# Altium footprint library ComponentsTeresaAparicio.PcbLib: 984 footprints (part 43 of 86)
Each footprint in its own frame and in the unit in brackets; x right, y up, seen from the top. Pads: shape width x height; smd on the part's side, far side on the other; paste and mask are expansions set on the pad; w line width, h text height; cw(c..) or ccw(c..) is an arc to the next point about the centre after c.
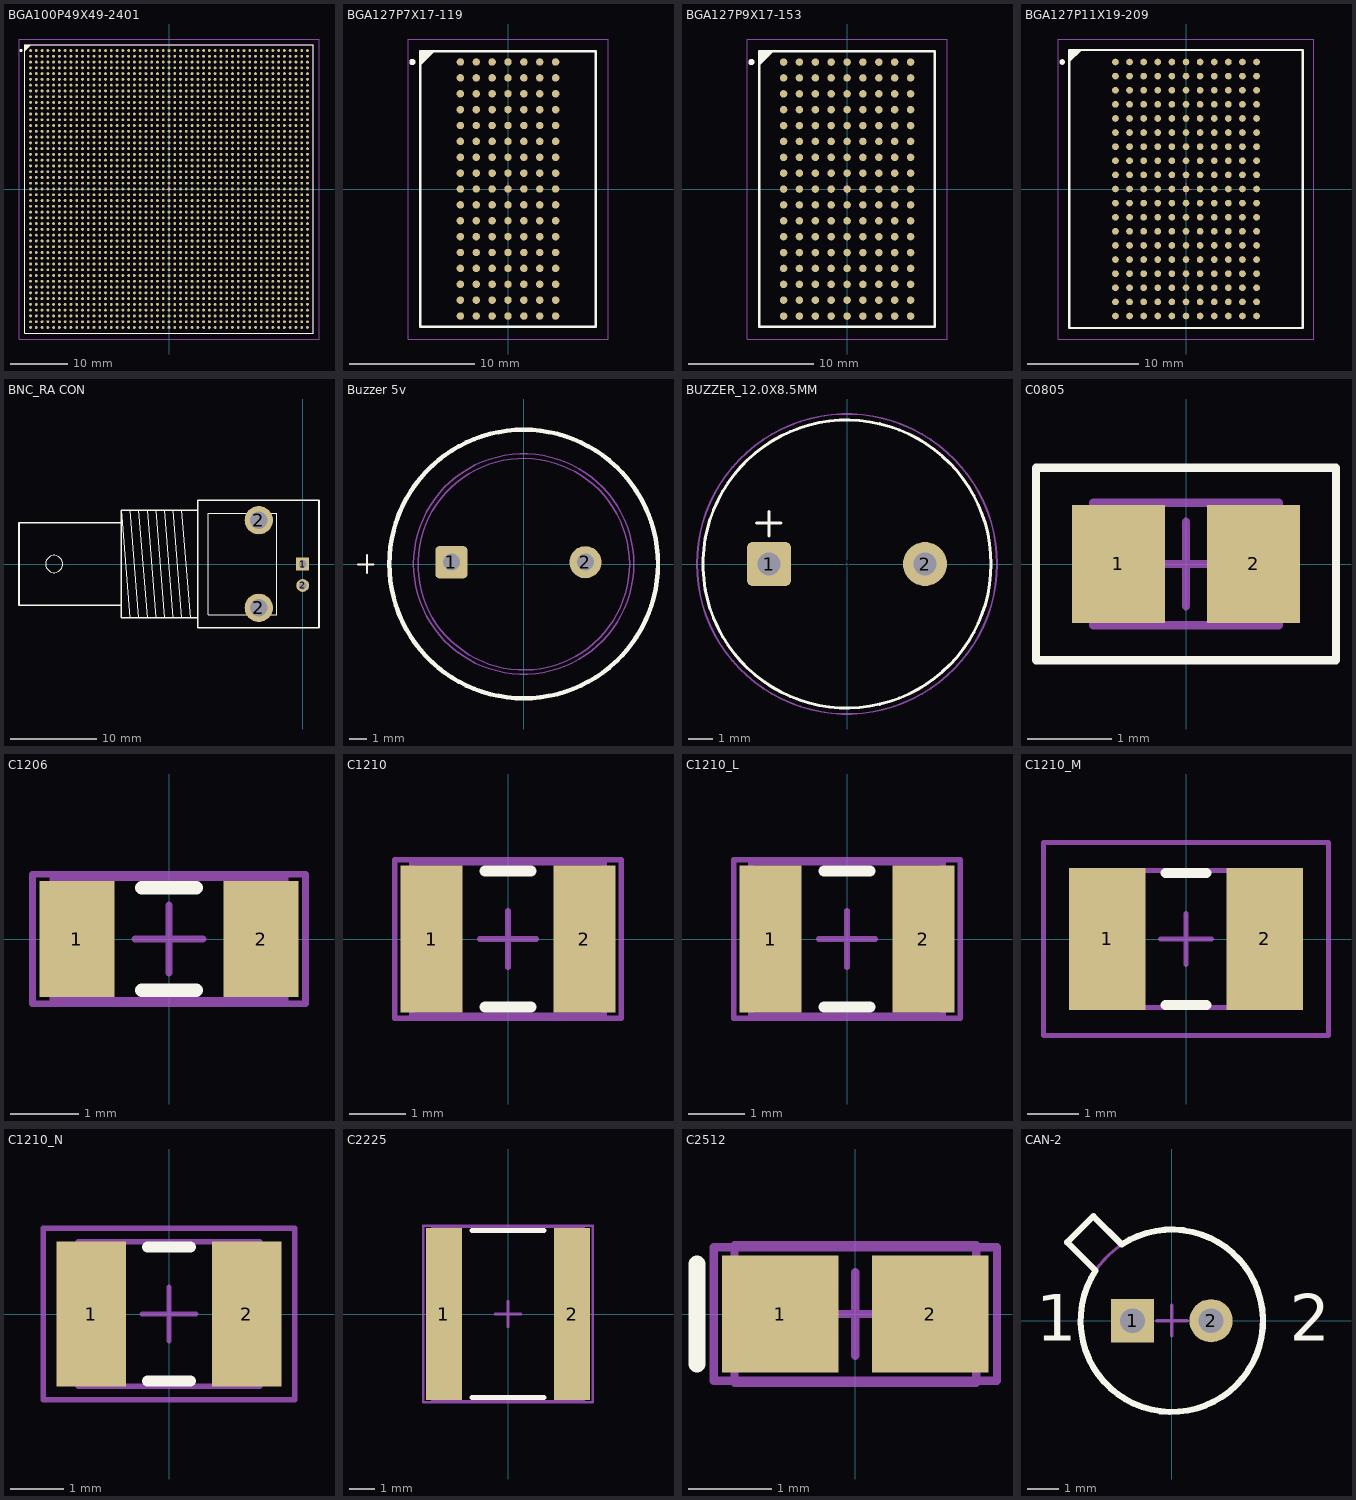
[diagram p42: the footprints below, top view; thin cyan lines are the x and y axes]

## BGA100P49X49-2401 [mm] "BGA, 2401-Leads, Body 50x50mm, Pitch 1mm"
height 3.5
pads (2401):
  round 0.5 smd: A1(-24,24) A2(-23,24) A3(-22,24) A4(-21,24) A5(-20,24) A6(-19,24) A7(-18,24) A8(-17,24) A9(-16,24) A10(-15,24) A11(-14,24) A12(-13,24) A13(-12,24) A14(-11,24) A15(-10,24) A16(-9,24) A17(-8,24) A18(-7,24) A19(-6,24) A20(-5,24) A21(-4,24) A22(-3,24) A23(-2,24) A24(-1,24) A25(0,24) A26(1,24) A27(2,24) A28(3,24) A29(4,24) A30(5,24) A31(6,24) A32(7,24) A33(8,24) A34(9,24) A35(10,24) A36(11,24) A37(12,24) A38(13,24) A39(14,24) A40(15,24) A41(16,24) A42(17,24) A43(18,24) A44(19,24) A45(20,24) A46(21,24) A47(22,24) A48(23,24) A49(24,24) AA1(-24,4) AA2(-23,4) AA3(-22,4) AA4(-21,4) AA5(-20,4) AA6(-19,4) AA7(-18,4) AA8(-17,4) AA9(-16,4) AA10(-15,4) AA11(-14,4) AA12(-13,4) AA13(-12,4) AA14(-11,4) AA15(-10,4) AA16(-9,4) AA17(-8,4) AA18(-7,4) AA19(-6,4) AA20(-5,4) AA21(-4,4) AA22(-3,4) AA23(-2,4) AA24(-1,4) AA25(0,4) AA26(1,4) AA27(2,4) AA28(3,4) AA29(4,4) AA30(5,4) AA31(6,4) AA32(7,4) AA33(8,4) AA34(9,4) AA35(10,4) AA36(11,4) AA37(12,4) AA38(13,4) AA39(14,4) AA40(15,4) AA41(16,4) AA42(17,4) AA43(18,4) AA44(19,4) AA45(20,4) AA46(21,4) AA47(22,4) AA48(23,4) AA49(24,4) AB1(-24,3) AB2(-23,3) AB3(-22,3) AB4(-21,3) AB5(-20,3) AB6(-19,3) AB7(-18,3) AB8(-17,3) AB9(-16,3) AB10(-15,3) AB11(-14,3) AB12(-13,3) AB13(-12,3) AB14(-11,3) AB15(-10,3) AB16(-9,3) AB17(-8,3) AB18(-7,3) AB19(-6,3) AB20(-5,3) AB21(-4,3) AB22(-3,3) AB23(-2,3) AB24(-1,3) AB25(0,3) AB26(1,3) AB27(2,3) AB28(3,3) AB29(4,3) AB30(5,3) AB31(6,3) AB32(7,3) AB33(8,3) AB34(9,3) AB35(10,3) AB36(11,3) AB37(12,3) AB38(13,3) AB39(14,3) AB40(15,3) AB41(16,3) AB42(17,3) AB43(18,3) AB44(19,3) AB45(20,3) AB46(21,3) AB47(22,3) AB48(23,3) AB49(24,3) AC1(-24,2) AC2(-23,2) AC3(-22,2) AC4(-21,2) AC5(-20,2) AC6(-19,2) AC7(-18,2) AC8(-17,2) AC9(-16,2) AC10(-15,2) AC11(-14,2) AC12(-13,2) AC13(-12,2) AC14(-11,2) AC15(-10,2) AC16(-9,2) AC17(-8,2) AC18(-7,2) AC19(-6,2) AC20(-5,2) AC21(-4,2) AC22(-3,2) AC23(-2,2) AC24(-1,2) AC25(0,2) AC26(1,2) AC27(2,2) AC28(3,2) AC29(4,2) AC30(5,2) AC31(6,2) AC32(7,2) AC33(8,2) AC34(9,2) AC35(10,2) AC36(11,2) AC37(12,2) AC38(13,2) AC39(14,2) AC40(15,2) AC41(16,2) AC42(17,2) AC43(18,2) AC44(19,2) AC45(20,2) AC46(21,2) AC47(22,2) AC48(23,2) AC49(24,2) AD1(-24,1) AD2(-23,1) AD3(-22,1) AD4(-21,1) AD5(-20,1) AD6(-19,1) AD7(-18,1) AD8(-17,1) AD9(-16,1) AD10(-15,1) AD11(-14,1) AD12(-13,1) AD13(-12,1) AD14(-11,1) AD15(-10,1) AD16(-9,1) AD17(-8,1) AD18(-7,1) AD19(-6,1) AD20(-5,1) AD21(-4,1) AD22(-3,1) AD23(-2,1) AD24(-1,1) AD25(0,1) AD26(1,1) AD27(2,1) AD28(3,1) AD29(4,1) AD30(5,1) AD31(6,1) AD32(7,1) AD33(8,1) AD34(9,1) AD35(10,1) AD36(11,1) AD37(12,1) AD38(13,1) AD39(14,1) AD40(15,1) AD41(16,1) AD42(17,1) AD43(18,1) AD44(19,1) AD45(20,1) AD46(21,1) AD47(22,1) AD48(23,1) AD49(24,1) AE1(-24,0) AE2(-23,0) AE3(-22,0) AE4(-21,0) AE5(-20,0) AE6(-19,0) AE7(-18,0) AE8(-17,0) AE9(-16,0) AE10(-15,0) AE11(-14,0) AE12(-13,0) AE13(-12,0) AE14(-11,0) AE15(-10,0) AE16(-9,0) AE17(-8,0) AE18(-7,0) AE19(-6,0) AE20(-5,0) AE21(-4,0) AE22(-3,0) AE23(-2,0) AE24(-1,0) AE25(0,0) AE26(1,0) AE27(2,0) AE28(3,0) AE29(4,0) AE30(5,0) AE31(6,0) AE32(7,0) AE33(8,0) AE34(9,0) AE35(10,0) AE36(11,0) AE37(12,0) AE38(13,0) AE39(14,0) AE40(15,0) AE41(16,0) AE42(17,0) AE43(18,0) AE44(19,0) AE45(20,0) AE46(21,0) AE47(22,0) AE48(23,0) AE49(24,0) AF1(-24,-1) AF2(-23,-1) AF3(-22,-1) AF4(-21,-1) AF5(-20,-1) AF6(-19,-1) AF7(-18,-1) AF8(-17,-1) AF9(-16,-1) AF10(-15,-1) AF11(-14,-1) AF12(-13,-1) AF13(-12,-1) AF14(-11,-1) AF15(-10,-1) AF16(-9,-1) AF17(-8,-1) AF18(-7,-1) AF19(-6,-1) AF20(-5,-1) AF21(-4,-1) AF22(-3,-1) AF23(-2,-1) AF24(-1,-1) AF25(0,-1) AF26(1,-1) AF27(2,-1) AF28(3,-1) AF29(4,-1) AF30(5,-1) AF31(6,-1) AF32(7,-1) AF33(8,-1) AF34(9,-1) AF35(10,-1) AF36(11,-1) AF37(12,-1) AF38(13,-1) AF39(14,-1) AF40(15,-1) AF41(16,-1) AF42(17,-1) AF43(18,-1) AF44(19,-1) AF45(20,-1) AF46(21,-1) AF47(22,-1) AF48(23,-1) AF49(24,-1) AG1(-24,-2) AG2(-23,-2) AG3(-22,-2) AG4(-21,-2) AG5(-20,-2) AG6(-19,-2) AG7(-18,-2) AG8(-17,-2) AG9(-16,-2) AG10(-15,-2) AG11(-14,-2) AG12(-13,-2) AG13(-12,-2) AG14(-11,-2) AG15(-10,-2) AG16(-9,-2) AG17(-8,-2) AG18(-7,-2) AG19(-6,-2) AG20(-5,-2) AG21(-4,-2) AG22(-3,-2) AG23(-2,-2) AG24(-1,-2) AG25(0,-2) AG26(1,-2) AG27(2,-2) AG28(3,-2) AG29(4,-2) AG30(5,-2) AG31(6,-2) AG32(7,-2) AG33(8,-2) AG34(9,-2) AG35(10,-2) AG36(11,-2) AG37(12,-2) AG38(13,-2) AG39(14,-2) AG40(15,-2) AG41(16,-2) AG42(17,-2) AG43(18,-2) AG44(19,-2) AG45(20,-2) AG46(21,-2) AG47(22,-2) AG48(23,-2) AG49(24,-2) AH1(-24,-3) AH2(-23,-3) AH3(-22,-3) AH4(-21,-3) AH5(-20,-3) AH6(-19,-3) AH7(-18,-3) AH8(-17,-3) AH9(-16,-3) AH10(-15,-3) AH11(-14,-3) AH12(-13,-3) AH13(-12,-3) AH14(-11,-3) AH15(-10,-3) AH16(-9,-3) AH17(-8,-3) AH18(-7,-3) AH19(-6,-3) AH20(-5,-3) AH21(-4,-3) AH22(-3,-3) AH23(-2,-3) AH24(-1,-3) AH25(0,-3) AH26(1,-3) AH27(2,-3) AH28(3,-3) AH29(4,-3) AH30(5,-3) AH31(6,-3) AH32(7,-3) AH33(8,-3) AH34(9,-3) AH35(10,-3) AH36(11,-3) AH37(12,-3) AH38(13,-3) AH39(14,-3) AH40(15,-3) AH41(16,-3) AH42(17,-3) AH43(18,-3) AH44(19,-3) AH45(20,-3) AH46(21,-3) AH47(22,-3) AH48(23,-3) AH49(24,-3) AJ1(-24,-4) AJ2(-23,-4) AJ3(-22,-4) AJ4(-21,-4) AJ5(-20,-4) AJ6(-19,-4) AJ7(-18,-4) AJ8(-17,-4) AJ9(-16,-4) AJ10(-15,-4) AJ11(-14,-4) AJ12(-13,-4) AJ13(-12,-4) AJ14(-11,-4) AJ15(-10,-4) AJ16(-9,-4) AJ17(-8,-4) AJ18(-7,-4) AJ19(-6,-4) AJ20(-5,-4) AJ21(-4,-4) AJ22(-3,-4) AJ23(-2,-4) AJ24(-1,-4) AJ25(0,-4) AJ26(1,-4) AJ27(2,-4) AJ28(3,-4) AJ29(4,-4) AJ30(5,-4) AJ31(6,-4) AJ32(7,-4) AJ33(8,-4) AJ34(9,-4) AJ35(10,-4) AJ36(11,-4) AJ37(12,-4) AJ38(13,-4) AJ39(14,-4) AJ40(15,-4) AJ41(16,-4) AJ42(17,-4) AJ43(18,-4) AJ44(19,-4) AJ45(20,-4) AJ46(21,-4) AJ47(22,-4) AJ48(23,-4) AJ49(24,-4) AK1(-24,-5) AK2(-23,-5) AK3(-22,-5) AK4(-21,-5) AK5(-20,-5) AK6(-19,-5) AK7(-18,-5) AK8(-17,-5) AK9(-16,-5) AK10(-15,-5) AK11(-14,-5) AK12(-13,-5) AK13(-12,-5) AK14(-11,-5) AK15(-10,-5) AK16(-9,-5) AK17(-8,-5) AK18(-7,-5) AK19(-6,-5) AK20(-5,-5) AK21(-4,-5) AK22(-3,-5) AK23(-2,-5) AK24(-1,-5) AK25(0,-5) AK26(1,-5) AK27(2,-5) AK28(3,-5) AK29(4,-5) AK30(5,-5) AK31(6,-5) AK32(7,-5) AK33(8,-5) AK34(9,-5) AK35(10,-5) AK36(11,-5) AK37(12,-5) AK38(13,-5) AK39(14,-5) AK40(15,-5) AK41(16,-5) AK42(17,-5) AK43(18,-5) AK44(19,-5) AK45(20,-5) AK46(21,-5) AK47(22,-5) AK48(23,-5) AK49(24,-5) AL1(-24,-6) AL2(-23,-6) AL3(-22,-6) AL4(-21,-6) AL5(-20,-6) AL6(-19,-6) AL7(-18,-6) AL8(-17,-6) AL9(-16,-6) AL10(-15,-6) AL11(-14,-6) AL12(-13,-6) AL13(-12,-6) AL14(-11,-6) AL15(-10,-6) AL16(-9,-6) AL17(-8,-6) AL18(-7,-6) AL19(-6,-6) AL20(-5,-6) AL21(-4,-6) AL22(-3,-6) AL23(-2,-6) AL24(-1,-6) AL25(0,-6) AL26(1,-6) AL27(2,-6) AL28(3,-6) AL29(4,-6) AL30(5,-6) AL31(6,-6) AL32(7,-6) AL33(8,-6) AL34(9,-6) AL35(10,-6) AL36(11,-6) AL37(12,-6) AL38(13,-6) AL39(14,-6) AL40(15,-6) AL41(16,-6) AL42(17,-6) AL43(18,-6) AL44(19,-6) AL45(20,-6) AL46(21,-6) AL47(22,-6) AL48(23,-6) AL49(24,-6) AM1(-24,-7) AM2(-23,-7) AM3(-22,-7) AM4(-21,-7) AM5(-20,-7) AM6(-19,-7) AM7(-18,-7) AM8(-17,-7) AM9(-16,-7) AM10(-15,-7) AM11(-14,-7) AM12(-13,-7) AM13(-12,-7) AM14(-11,-7) AM15(-10,-7) AM16(-9,-7) AM17(-8,-7) AM18(-7,-7) AM19(-6,-7) AM20(-5,-7) AM21(-4,-7) AM22(-3,-7) AM23(-2,-7) AM24(-1,-7) AM25(0,-7) AM26(1,-7) AM27(2,-7) AM28(3,-7) AM29(4,-7) AM30(5,-7) AM31(6,-7) AM32(7,-7) AM33(8,-7) AM34(9,-7) AM35(10,-7) AM36(11,-7) AM37(12,-7) AM38(13,-7) AM39(14,-7) AM40(15,-7) AM41(16,-7) AM42(17,-7) AM43(18,-7) AM44(19,-7) AM45(20,-7) AM46(21,-7) AM47(22,-7) AM48(23,-7) AM49(24,-7) AN1(-24,-8) AN2(-23,-8) AN3(-22,-8) AN4(-21,-8) AN5(-20,-8) AN6(-19,-8) AN7(-18,-8) AN8(-17,-8) AN9(-16,-8) AN10(-15,-8) AN11(-14,-8) AN12(-13,-8) AN13(-12,-8) AN14(-11,-8) AN15(-10,-8) AN16(-9,-8) AN17(-8,-8) AN18(-7,-8) AN19(-6,-8) AN20(-5,-8) AN21(-4,-8) AN22(-3,-8) AN23(-2,-8) AN24(-1,-8) AN25(0,-8) AN26(1,-8) AN27(2,-8) AN28(3,-8) AN29(4,-8) AN30(5,-8) AN31(6,-8) AN32(7,-8) AN33(8,-8) AN34(9,-8) AN35(10,-8) AN36(11,-8) AN37(12,-8) AN38(13,-8) AN39(14,-8) AN40(15,-8) AN41(16,-8) AN42(17,-8) AN43(18,-8) AN44(19,-8) AN45(20,-8) AN46(21,-8) AN47(22,-8) AN48(23,-8) AN49(24,-8) AP1(-24,-9) AP2(-23,-9) AP3(-22,-9) AP4(-21,-9) AP5(-20,-9) AP6(-19,-9) AP7(-18,-9) AP8(-17,-9) AP9(-16,-9) AP10(-15,-9) AP11(-14,-9) AP12(-13,-9) AP13(-12,-9) AP14(-11,-9) AP15(-10,-9) AP16(-9,-9) AP17(-8,-9) AP18(-7,-9) AP19(-6,-9) AP20(-5,-9) AP21(-4,-9) AP22(-3,-9) AP23(-2,-9) AP24(-1,-9) AP25(0,-9) AP26(1,-9) AP27(2,-9) AP28(3,-9) AP29(4,-9) AP30(5,-9) AP31(6,-9) AP32(7,-9) AP33(8,-9) AP34(9,-9) AP35(10,-9) AP36(11,-9) AP37(12,-9) AP38(13,-9) AP39(14,-9) AP40(15,-9) AP41(16,-9) AP42(17,-9) AP43(18,-9) AP44(19,-9) AP45(20,-9) AP46(21,-9) AP47(22,-9) AP48(23,-9) AP49(24,-9) AR1(-24,-10) AR2(-23,-10) AR3(-22,-10) AR4(-21,-10) AR5(-20,-10) AR6(-19,-10) AR7(-18,-10) AR8(-17,-10) AR9(-16,-10) AR10(-15,-10) AR11(-14,-10) AR12(-13,-10) AR13(-12,-10) AR14(-11,-10) AR15(-10,-10) AR16(-9,-10) AR17(-8,-10) AR18(-7,-10) AR19(-6,-10) AR20(-5,-10) AR21(-4,-10) AR22(-3,-10) AR23(-2,-10) AR24(-1,-10) AR25(0,-10) AR26(1,-10) AR27(2,-10) AR28(3,-10) AR29(4,-10) AR30(5,-10) AR31(6,-10) AR32(7,-10) AR33(8,-10) AR34(9,-10) AR35(10,-10) AR36(11,-10) AR37(12,-10) AR38(13,-10) AR39(14,-10) AR40(15,-10) AR41(16,-10) AR42(17,-10) AR43(18,-10) AR44(19,-10) AR45(20,-10) AR46(21,-10) AR47(22,-10) AR48(23,-10) AR49(24,-10) AT1(-24,-11) AT2(-23,-11) AT3(-22,-11) AT4(-21,-11) AT5(-20,-11) AT6(-19,-11) AT7(-18,-11) AT8(-17,-11) AT9(-16,-11) AT10(-15,-11) AT11(-14,-11) AT12(-13,-11) AT13(-12,-11) AT14(-11,-11) AT15(-10,-11) AT16(-9,-11) AT17(-8,-11) AT18(-7,-11) AT19(-6,-11) AT20(-5,-11) AT21(-4,-11) AT22(-3,-11) AT23(-2,-11) AT24(-1,-11) AT25(0,-11) AT26(1,-11) AT27(2,-11) AT28(3,-11) AT29(4,-11) AT30(5,-11) AT31(6,-11) AT32(7,-11) AT33(8,-11) AT34(9,-11) AT35(10,-11) AT36(11,-11) AT37(12,-11) AT38(13,-11) AT39(14,-11) AT40(15,-11) AT41(16,-11) AT42(17,-11) AT43(18,-11) AT44(19,-11) AT45(20,-11) AT46(21,-11) AT47(22,-11) AT48(23,-11) AT49(24,-11) AU1(-24,-12) AU2(-23,-12) AU3(-22,-12) AU4(-21,-12) AU5(-20,-12) AU6(-19,-12) AU7(-18,-12) AU8(-17,-12) AU9(-16,-12) AU10(-15,-12) AU11(-14,-12) AU12(-13,-12) AU13(-12,-12) AU14(-11,-12) AU15(-10,-12) AU16(-9,-12) AU17(-8,-12) AU18(-7,-12) AU19(-6,-12) AU20(-5,-12) AU21(-4,-12) AU22(-3,-12) AU23(-2,-12) AU24(-1,-12) AU25(0,-12) AU26(1,-12) AU27(2,-12) AU28(3,-12) AU29(4,-12) AU30(5,-12) AU31(6,-12) AU32(7,-12) AU33(8,-12) AU34(9,-12) AU35(10,-12) AU36(11,-12) AU37(12,-12) AU38(13,-12) AU39(14,-12) AU40(15,-12) AU41(16,-12) AU42(17,-12) AU43(18,-12) AU44(19,-12) AU45(20,-12) AU46(21,-12) AU47(22,-12) AU48(23,-12) AU49(24,-12) AV1(-24,-13) AV2(-23,-13) AV3(-22,-13) AV4(-21,-13) AV5(-20,-13) AV6(-19,-13) AV7(-18,-13) AV8(-17,-13) AV9(-16,-13) AV10(-15,-13) AV11(-14,-13) AV12(-13,-13) AV13(-12,-13) AV14(-11,-13) AV15(-10,-13) AV16(-9,-13) AV17(-8,-13) AV18(-7,-13) AV19(-6,-13) AV20(-5,-13) AV21(-4,-13) AV22(-3,-13) AV23(-2,-13) AV24(-1,-13) AV25(0,-13) AV26(1,-13) AV27(2,-13) AV28(3,-13) AV29(4,-13) AV30(5,-13) AV31(6,-13) AV32(7,-13) AV33(8,-13) AV34(9,-13) AV35(10,-13) AV36(11,-13) AV37(12,-13) AV38(13,-13) AV39(14,-13) AV40(15,-13) AV41(16,-13) AV42(17,-13) AV43(18,-13) AV44(19,-13) AV45(20,-13) AV46(21,-13) AV47(22,-13) AV48(23,-13) AV49(24,-13) AW1(-24,-14) AW2(-23,-14) AW3(-22,-14) AW4(-21,-14) AW5(-20,-14) AW6(-19,-14) AW7(-18,-14) AW8(-17,-14) AW9(-16,-14) AW10(-15,-14) AW11(-14,-14) AW12(-13,-14) AW13(-12,-14) AW14(-11,-14) AW15(-10,-14) AW16(-9,-14) AW17(-8,-14) AW18(-7,-14) AW19(-6,-14) AW20(-5,-14) AW21(-4,-14) AW22(-3,-14) AW23(-2,-14) AW24(-1,-14) AW25(0,-14) AW26(1,-14) AW27(2,-14) AW28(3,-14) AW29(4,-14) AW30(5,-14) AW31(6,-14) AW32(7,-14) AW33(8,-14) AW34(9,-14) AW35(10,-14) AW36(11,-14) AW37(12,-14) AW38(13,-14) AW39(14,-14) AW40(15,-14) AW41(16,-14) AW42(17,-14) AW43(18,-14) AW44(19,-14) AW45(20,-14) AW46(21,-14) AW47(22,-14) AW48(23,-14) AW49(24,-14) AY1(-24,-15) AY2(-23,-15) AY3(-22,-15) AY4(-21,-15) AY5(-20,-15) AY6(-19,-15) AY7(-18,-15) AY8(-17,-15) AY9(-16,-15) AY10(-15,-15) AY11(-14,-15) AY12(-13,-15) AY13(-12,-15) AY14(-11,-15) AY15(-10,-15) AY16(-9,-15) AY17(-8,-15) AY18(-7,-15) AY19(-6,-15) AY20(-5,-15) AY21(-4,-15) AY22(-3,-15) AY23(-2,-15) AY24(-1,-15) AY25(0,-15) AY26(1,-15) AY27(2,-15) AY28(3,-15) AY29(4,-15) AY30(5,-15) AY31(6,-15) AY32(7,-15) AY33(8,-15) AY34(9,-15) AY35(10,-15) AY36(11,-15) AY37(12,-15) AY38(13,-15) AY39(14,-15) AY40(15,-15) AY41(16,-15) AY42(17,-15) AY43(18,-15) AY44(19,-15) AY45(20,-15) AY46(21,-15) AY47(22,-15) AY48(23,-15) AY49(24,-15) B1(-24,23) B2(-23,23) B3(-22,23) B4(-21,23) B5(-20,23) B6(-19,23) B7(-18,23) B8(-17,23) B9(-16,23) B10(-15,23) B11(-14,23) B12(-13,23) B13(-12,23) B14(-11,23) B15(-10,23) B16(-9,23) B17(-8,23) B18(-7,23) B19(-6,23) B20(-5,23) B21(-4,23) B22(-3,23) B23(-2,23) B24(-1,23) B25(0,23) B26(1,23) B27(2,23) B28(3,23) B29(4,23) B30(5,23) B31(6,23) B32(7,23) B33(8,23) B34(9,23) B35(10,23) B36(11,23) B37(12,23) B38(13,23) B39(14,23) B40(15,23) B41(16,23) B42(17,23) B43(18,23) B44(19,23) B45(20,23) B46(21,23) B47(22,23) B48(23,23) B49(24,23) BA1(-24,-16) BA2(-23,-16) BA3(-22,-16) BA4(-21,-16) BA5(-20,-16) BA6(-19,-16) BA7(-18,-16) BA8(-17,-16) BA9(-16,-16) BA10(-15,-16) BA11(-14,-16) BA12(-13,-16) BA13(-12,-16) BA14(-11,-16) BA15(-10,-16) BA16(-9,-16) BA17(-8,-16) BA18(-7,-16) BA19(-6,-16) BA20(-5,-16) BA21(-4,-16) BA22(-3,-16) BA23(-2,-16) BA24(-1,-16) BA25(0,-16) BA26(1,-16) BA27(2,-16) BA28(3,-16) BA29(4,-16) BA30(5,-16) BA31(6,-16) BA32(7,-16) BA33(8,-16) BA34(9,-16) BA35(10,-16) BA36(11,-16) BA37(12,-16) BA38(13,-16) BA39(14,-16) BA40(15,-16) BA41(16,-16) BA42(17,-16) BA43(18,-16) BA44(19,-16) BA45(20,-16) BA46(21,-16) BA47(22,-16) BA48(23,-16) BA49(24,-16) BB1(-24,-17) BB2(-23,-17) BB3(-22,-17) BB4(-21,-17) BB5(-20,-17) BB6(-19,-17) BB7(-18,-17) BB8(-17,-17) BB9(-16,-17) BB10(-15,-17) BB11(-14,-17) BB12(-13,-17) BB13(-12,-17) BB14(-11,-17) BB15(-10,-17) BB16(-9,-17) BB17(-8,-17) BB18(-7,-17) BB19(-6,-17) BB20(-5,-17) BB21(-4,-17) BB22(-3,-17) BB23(-2,-17) BB24(-1,-17) BB25(0,-17) BB26(1,-17) BB27(2,-17) BB28(3,-17) BB29(4,-17) BB30(5,-17) BB31(6,-17) BB32(7,-17) BB33(8,-17) BB34(9,-17) BB35(10,-17) BB36(11,-17) BB37(12,-17) BB38(13,-17) BB39(14,-17) BB40(15,-17) BB41(16,-17) BB42(17,-17) BB43(18,-17) BB44(19,-17) BB45(20,-17) BB46(21,-17) BB47(22,-17) BB48(23,-17) BB49(24,-17) BC1(-24,-18) BC2(-23,-18) BC3(-22,-18) BC4(-21,-18) BC5(-20,-18) BC6(-19,-18) BC7(-18,-18) BC8(-17,-18) BC9(-16,-18) BC10(-15,-18) BC11(-14,-18) BC12(-13,-18) BC13(-12,-18) BC14(-11,-18) BC15(-10,-18) BC16(-9,-18) BC17(-8,-18) BC18(-7,-18) BC19(-6,-18) BC20(-5,-18) BC21(-4,-18) BC22(-3,-18) BC23(-2,-18) BC24(-1,-18) BC25(0,-18) BC26(1,-18) BC27(2,-18) BC28(3,-18) BC29(4,-18) BC30(5,-18) BC31(6,-18) BC32(7,-18) BC33(8,-18) BC34(9,-18) BC35(10,-18) BC36(11,-18) BC37(12,-18) BC38(13,-18) BC39(14,-18) BC40(15,-18) BC41(16,-18) BC42(17,-18) BC43(18,-18) BC44(19,-18) BC45(20,-18) BC46(21,-18) BC47(22,-18) BC48(23,-18) BC49(24,-18) BD1(-24,-19) BD2(-23,-19) BD3(-22,-19) BD4(-21,-19) BD5(-20,-19) BD6(-19,-19) BD7(-18,-19) BD8(-17,-19) BD9(-16,-19) BD10(-15,-19) BD11(-14,-19) BD12(-13,-19) BD13(-12,-19) BD14(-11,-19) BD15(-10,-19) BD16(-9,-19) BD17(-8,-19) BD18(-7,-19) BD19(-6,-19) BD20(-5,-19) BD21(-4,-19) BD22(-3,-19) BD23(-2,-19) BD24(-1,-19) BD25(0,-19) BD26(1,-19) BD27(2,-19) BD28(3,-19) BD29(4,-19) BD30(5,-19) BD31(6,-19) BD32(7,-19) BD33(8,-19) BD34(9,-19) BD35(10,-19) BD36(11,-19) BD37(12,-19) BD38(13,-19) BD39(14,-19) BD40(15,-19) BD41(16,-19) BD42(17,-19) BD43(18,-19) BD44(19,-19) BD45(20,-19) BD46(21,-19) BD47(22,-19) BD48(23,-19) BD49(24,-19) BE1(-24,-20) BE2(-23,-20) BE3(-22,-20) BE4(-21,-20) BE5(-20,-20) BE6(-19,-20) BE7(-18,-20) BE8(-17,-20) BE9(-16,-20) BE10(-15,-20) BE11(-14,-20) BE12(-13,-20) BE13(-12,-20) BE14(-11,-20) BE15(-10,-20) BE16(-9,-20) BE17(-8,-20) BE18(-7,-20) BE19(-6,-20) BE20(-5,-20) BE21(-4,-20) BE22(-3,-20) BE23(-2,-20) BE24(-1,-20) BE25(0,-20) BE26(1,-20) BE27(2,-20) BE28(3,-20) BE29(4,-20) BE30(5,-20) BE31(6,-20) BE32(7,-20) BE33(8,-20) BE34(9,-20) BE35(10,-20) BE36(11,-20) BE37(12,-20) BE38(13,-20) BE39(14,-20) BE40(15,-20) BE41(16,-20) BE42(17,-20) BE43(18,-20) BE44(19,-20) BE45(20,-20) BE46(21,-20) BE47(22,-20) BE48(23,-20) BE49(24,-20) BF1(-24,-21) BF2(-23,-21) BF3(-22,-21) BF4(-21,-21) BF5(-20,-21) BF6(-19,-21) BF7(-18,-21) BF8(-17,-21) BF9(-16,-21) BF10(-15,-21) BF11(-14,-21) BF12(-13,-21) BF13(-12,-21) BF14(-11,-21) BF15(-10,-21) BF16(-9,-21) BF17(-8,-21) BF18(-7,-21) BF19(-6,-21) BF20(-5,-21) BF21(-4,-21) BF22(-3,-21) BF23(-2,-21) BF24(-1,-21) BF25(0,-21) BF26(1,-21) BF27(2,-21) BF28(3,-21) BF29(4,-21) BF30(5,-21) BF31(6,-21) BF32(7,-21) BF33(8,-21) BF34(9,-21) BF35(10,-21) BF36(11,-21) BF37(12,-21) BF38(13,-21) BF39(14,-21) BF40(15,-21) BF41(16,-21) BF42(17,-21) BF43(18,-21) BF44(19,-21) BF45(20,-21) BF46(21,-21) BF47(22,-21) BF48(23,-21) BF49(24,-21) BG1(-24,-22) BG2(-23,-22) BG3(-22,-22) BG4(-21,-22) BG5(-20,-22) BG6(-19,-22) BG7(-18,-22) BG8(-17,-22) BG9(-16,-22) BG10(-15,-22) BG11(-14,-22) BG12(-13,-22) BG13(-12,-22) BG14(-11,-22) BG15(-10,-22) BG16(-9,-22) BG17(-8,-22) BG18(-7,-22) BG19(-6,-22) BG20(-5,-22) BG21(-4,-22) BG22(-3,-22) BG23(-2,-22) BG24(-1,-22) BG25(0,-22) BG26(1,-22) BG27(2,-22) BG28(3,-22) BG29(4,-22) BG30(5,-22) BG31(6,-22) BG32(7,-22) BG33(8,-22) BG34(9,-22) BG35(10,-22) BG36(11,-22) BG37(12,-22) BG38(13,-22) BG39(14,-22) BG40(15,-22) BG41(16,-22) BG42(17,-22) BG43(18,-22) BG44(19,-22) BG45(20,-22) BG46(21,-22) BG47(22,-22) BG48(23,-22) BG49(24,-22) BH1(-24,-23) BH2(-23,-23) BH3(-22,-23) BH4(-21,-23) BH5(-20,-23) BH6(-19,-23) BH7(-18,-23) BH8(-17,-23) BH9(-16,-23) BH10(-15,-23) BH11(-14,-23) BH12(-13,-23) BH13(-12,-23) BH14(-11,-23) BH15(-10,-23) BH16(-9,-23) BH17(-8,-23) BH18(-7,-23) BH19(-6,-23) BH20(-5,-23) BH21(-4,-23) BH22(-3,-23) BH23(-2,-23) BH24(-1,-23) BH25(0,-23) BH26(1,-23) BH27(2,-23) BH28(3,-23) BH29(4,-23) BH30(5,-23) BH31(6,-23) BH32(7,-23) BH33(8,-23) BH34(9,-23) BH35(10,-23) BH36(11,-23) BH37(12,-23) BH38(13,-23) BH39(14,-23) BH40(15,-23) BH41(16,-23) BH42(17,-23) BH43(18,-23) BH44(19,-23) BH45(20,-23) BH46(21,-23) BH47(22,-23) BH48(23,-23) BH49(24,-23) BJ1(-24,-24) BJ2(-23,-24) BJ3(-22,-24) BJ4(-21,-24) BJ5(-20,-24) BJ6(-19,-24) BJ7(-18,-24) BJ8(-17,-24) BJ9(-16,-24) BJ10(-15,-24) BJ11(-14,-24) BJ12(-13,-24) BJ13(-12,-24) BJ14(-11,-24) BJ15(-10,-24) BJ16(-9,-24) BJ17(-8,-24) BJ18(-7,-24) BJ19(-6,-24) BJ20(-5,-24) BJ21(-4,-24) BJ22(-3,-24) BJ23(-2,-24) BJ24(-1,-24) BJ25(0,-24) BJ26(1,-24) BJ27(2,-24) BJ28(3,-24) BJ29(4,-24) BJ30(5,-24) BJ31(6,-24) BJ32(7,-24) BJ33(8,-24) BJ34(9,-24) BJ35(10,-24) BJ36(11,-24) BJ37(12,-24) BJ38(13,-24) BJ39(14,-24) BJ40(15,-24) BJ41(16,-24) BJ42(17,-24) BJ43(18,-24) BJ44(19,-24) BJ45(20,-24) BJ46(21,-24) BJ47(22,-24) BJ48(23,-24) BJ49(24,-24) C1(-24,22) C2(-23,22) C3(-22,22) C4(-21,22) C5(-20,22) C6(-19,22) C7(-18,22) C8(-17,22) C9(-16,22) C10(-15,22) C11(-14,22) C12(-13,22) C13(-12,22) C14(-11,22) C15(-10,22) C16(-9,22) C17(-8,22) C18(-7,22) C19(-6,22) C20(-5,22) C21(-4,22) C22(-3,22) C23(-2,22) C24(-1,22) C25(0,22) C26(1,22) C27(2,22) C28(3,22) C29(4,22) C30(5,22) C31(6,22) C32(7,22) C33(8,22) C34(9,22) C35(10,22) C36(11,22) C37(12,22) C38(13,22) C39(14,22) C40(15,22) C41(16,22) C42(17,22) C43(18,22) C44(19,22) C45(20,22) C46(21,22) C47(22,22) C48(23,22) C49(24,22) D1(-24,21) D2(-23,21) D3(-22,21) D4(-21,21) D5(-20,21) D6(-19,21) D7(-18,21) D8(-17,21) D9(-16,21) D10(-15,21) D11(-14,21) D12(-13,21) D13(-12,21) D14(-11,21) D15(-10,21) D16(-9,21) D17(-8,21) D18(-7,21) D19(-6,21) D20(-5,21) D21(-4,21) D22(-3,21) D23(-2,21) D24(-1,21) D25(0,21) D26(1,21) D27(2,21) D28(3,21) D29(4,21) D30(5,21) D31(6,21) D32(7,21) D33(8,21) D34(9,21) D35(10,21) D36(11,21) D37(12,21) D38(13,21) D39(14,21) D40(15,21) D41(16,21) D42(17,21) D43(18,21) D44(19,21) D45(20,21) D46(21,21) D47(22,21) D48(23,21) D49(24,21) E1(-24,20) E2(-23,20) E3(-22,20) E4(-21,20) E5(-20,20) E6(-19,20) E7(-18,20) E8(-17,20) E9(-16,20) E10(-15,20) E11(-14,20) E12(-13,20) E13(-12,20) E14(-11,20) E15(-10,20) E16(-9,20) E17(-8,20) E18(-7,20) E19(-6,20) E20(-5,20) E21(-4,20) E22(-3,20) E23(-2,20) E24(-1,20) E25(0,20) E26(1,20) E27(2,20) E28(3,20) E29(4,20) E30(5,20) E31(6,20) E32(7,20) E33(8,20) E34(9,20) E35(10,20) E36(11,20) E37(12,20) E38(13,20) E39(14,20) E40(15,20) E41(16,20) E42(17,20) E43(18,20) E44(19,20) E45(20,20) E46(21,20) E47(22,20) E48(23,20) E49(24,20) F1(-24,19) F2(-23,19) F3(-22,19) F4(-21,19) F5(-20,19) F6(-19,19) F7(-18,19) F8(-17,19) F9(-16,19) F10(-15,19) F11(-14,19) F12(-13,19) F13(-12,19) F14(-11,19) F15(-10,19) F16(-9,19) F17(-8,19) F18(-7,19) F19(-6,19) F20(-5,19) F21(-4,19) F22(-3,19) F23(-2,19) F24(-1,19) F25(0,19) F26(1,19) F27(2,19) F28(3,19) F29(4,19) F30(5,19) F31(6,19) F32(7,19) F33(8,19) F34(9,19) F35(10,19) F36(11,19) F37(12,19) F38(13,19) F39(14,19) F40(15,19) F41(16,19) F42(17,19) F43(18,19) F44(19,19) F45(20,19) F46(21,19) F47(22,19) F48(23,19) F49(24,19) G1(-24,18) G2(-23,18) G3(-22,18) G4(-21,18) G5(-20,18) G6(-19,18) G7(-18,18) G8(-17,18) G9(-16,18) G10(-15,18) G11(-14,18) G12(-13,18) G13(-12,18) G14(-11,18) G15(-10,18) G16(-9,18) G17(-8,18) G18(-7,18) G19(-6,18) G20(-5,18) G21(-4,18) G22(-3,18) G23(-2,18) G24(-1,18) G25(0,18) G26(1,18) G27(2,18) G28(3,18) G29(4,18) G30(5,18) G31(6,18) G32(7,18) G33(8,18) G34(9,18) G35(10,18) G36(11,18) G37(12,18) G38(13,18) G39(14,18) G40(15,18) G41(16,18) G42(17,18) G43(18,18) G44(19,18) G45(20,18) G46(21,18) G47(22,18) G48(23,18) G49(24,18) H1(-24,17) H2(-23,17) H3(-22,17) H4(-21,17) H5(-20,17) H6(-19,17) H7(-18,17) H8(-17,17) H9(-16,17) H10(-15,17) H11(-14,17) H12(-13,17) H13(-12,17) H14(-11,17) H15(-10,17) H16(-9,17) H17(-8,17) H18(-7,17) H19(-6,17) H20(-5,17) H21(-4,17) H22(-3,17) H23(-2,17) H24(-1,17) H25(0,17) H26(1,17) H27(2,17) H28(3,17) H29(4,17) H30(5,17) H31(6,17) H32(7,17) H33(8,17) H34(9,17) H35(10,17) H36(11,17) H37(12,17) H38(13,17) H39(14,17) H40(15,17) H41(16,17) H42(17,17) H43(18,17) H44(19,17) H45(20,17) H46(21,17) H47(22,17) H48(23,17) H49(24,17) J1(-24,16) J2(-23,16) J3(-22,16) J4(-21,16) J5(-20,16) J6(-19,16) J7(-18,16) J8(-17,16) J9(-16,16) J10(-15,16) J11(-14,16) J12(-13,16) J13(-12,16) J14(-11,16) J15(-10,16) J16(-9,16) J17(-8,16) J18(-7,16) J19(-6,16) J20(-5,16) J21(-4,16) J22(-3,16) J23(-2,16) J24(-1,16) J25(0,16) J26(1,16) J27(2,16) J28(3,16) J29(4,16) J30(5,16) J31(6,16) J32(7,16) J33(8,16) J34(9,16) J35(10,16) J36(11,16) J37(12,16) J38(13,16) J39(14,16) J40(15,16) J41(16,16) J42(17,16) J43(18,16) J44(19,16) J45(20,16) J46(21,16) J47(22,16) J48(23,16) J49(24,16) K1(-24,15) K2(-23,15) K3(-22,15) K4(-21,15) K5(-20,15) K6(-19,15) K7(-18,15) K8(-17,15) K9(-16,15) K10(-15,15) K11(-14,15) K12(-13,15) K13(-12,15) K14(-11,15) K15(-10,15) K16(-9,15) K17(-8,15) K18(-7,15) K19(-6,15) K20(-5,15) K21(-4,15) K22(-3,15) K23(-2,15) K24(-1,15) K25(0,15) K26(1,15) K27(2,15) K28(3,15) K29(4,15) K30(5,15) K31(6,15) K32(7,15) K33(8,15) K34(9,15) K35(10,15) K36(11,15) K37(12,15) K38(13,15) K39(14,15) K40(15,15) K41(16,15) K42(17,15) K43(18,15) K44(19,15) K45(20,15) K46(21,15) K47(22,15) K48(23,15) K49(24,15) L1(-24,14) L2(-23,14) L3(-22,14) L4(-21,14) L5(-20,14) L6(-19,14) L7(-18,14) L8(-17,14) L9(-16,14) L10(-15,14) L11(-14,14) L12(-13,14) L13(-12,14) L14(-11,14) L15(-10,14) L16(-9,14) L17(-8,14) L18(-7,14) L19(-6,14) L20(-5,14) L21(-4,14) L22(-3,14) L23(-2,14) L24(-1,14) L25(0,14) L26(1,14) L27(2,14) L28(3,14) L29(4,14) L30(5,14) L31(6,14) L32(7,14) L33(8,14) L34(9,14) L35(10,14) L36(11,14) L37(12,14) L38(13,14) L39(14,14) L40(15,14) L41(16,14) L42(17,14) L43(18,14) L44(19,14) L45(20,14) L46(21,14) L47(22,14) L48(23,14) L49(24,14) M1(-24,13) M2(-23,13) M3(-22,13) M4(-21,13) M5(-20,13) M6(-19,13) M7(-18,13) M8(-17,13) M9(-16,13) M10(-15,13) M11(-14,13) M12(-13,13) M13(-12,13) M14(-11,13) M15(-10,13) M16(-9,13) M17(-8,13) M18(-7,13) M19(-6,13) M20(-5,13) M21(-4,13) M22(-3,13) M23(-2,13) M24(-1,13) M25(0,13) M26(1,13) M27(2,13) M28(3,13) M29(4,13) M30(5,13) M31(6,13) M32(7,13) M33(8,13) M34(9,13) M35(10,13) M36(11,13) M37(12,13) M38(13,13) M39(14,13) M40(15,13) M41(16,13) M42(17,13) M43(18,13) M44(19,13) M45(20,13) M46(21,13) M47(22,13) M48(23,13) M49(24,13) N1(-24,12) N2(-23,12) N3(-22,12) N4(-21,12) N5(-20,12) N6(-19,12) N7(-18,12) N8(-17,12) N9(-16,12) N10(-15,12) N11(-14,12) N12(-13,12) N13(-12,12) N14(-11,12) N15(-10,12) N16(-9,12) N17(-8,12) N18(-7,12) N19(-6,12) N20(-5,12) N21(-4,12) N22(-3,12) N23(-2,12) N24(-1,12) N25(0,12) N26(1,12) N27(2,12) N28(3,12) N29(4,12) N30(5,12) N31(6,12) N32(7,12) N33(8,12) N34(9,12) N35(10,12) N36(11,12) N37(12,12) N38(13,12) N39(14,12) N40(15,12) N41(16,12) N42(17,12) N43(18,12) N44(19,12) N45(20,12) N46(21,12) N47(22,12) N48(23,12) N49(24,12) P1(-24,11) P2(-23,11) P3(-22,11) P4(-21,11) P5(-20,11) P6(-19,11) P7(-18,11) P8(-17,11) P9(-16,11) P10(-15,11) P11(-14,11) P12(-13,11) P13(-12,11) P14(-11,11) P15(-10,11) P16(-9,11) P17(-8,11) P18(-7,11) P19(-6,11) P20(-5,11) P21(-4,11) P22(-3,11) P23(-2,11) P24(-1,11) P25(0,11) P26(1,11) P27(2,11) P28(3,11) P29(4,11) P30(5,11) P31(6,11) P32(7,11) P33(8,11) P34(9,11) P35(10,11) P36(11,11) P37(12,11) P38(13,11) P39(14,11) P40(15,11) P41(16,11) P42(17,11) P43(18,11) P44(19,11) P45(20,11) P46(21,11) P47(22,11) P48(23,11) P49(24,11) R1(-24,10) R2(-23,10) R3(-22,10) R4(-21,10) R5(-20,10) R6(-19,10) R7(-18,10) R8(-17,10) R9(-16,10) R10(-15,10) R11(-14,10) R12(-13,10) R13(-12,10) R14(-11,10) R15(-10,10) R16(-9,10) R17(-8,10) R18(-7,10) R19(-6,10) R20(-5,10) R21(-4,10) R22(-3,10) R23(-2,10) R24(-1,10) R25(0,10) R26(1,10) R27(2,10) R28(3,10) R29(4,10) R30(5,10) R31(6,10) R32(7,10) R33(8,10) R34(9,10) R35(10,10) R36(11,10) R37(12,10) R38(13,10) R39(14,10) R40(15,10) R41(16,10) R42(17,10) R43(18,10) R44(19,10) R45(20,10) R46(21,10) R47(22,10) R48(23,10) R49(24,10) T1(-24,9) T2(-23,9) T3(-22,9) T4(-21,9) T5(-20,9) T6(-19,9) T7(-18,9) T8(-17,9) T9(-16,9) T10(-15,9) T11(-14,9) T12(-13,9) T13(-12,9) T14(-11,9) T15(-10,9) T16(-9,9) T17(-8,9) T18(-7,9) T19(-6,9) T20(-5,9) T21(-4,9) T22(-3,9) T23(-2,9) T24(-1,9) T25(0,9) T26(1,9) T27(2,9) T28(3,9) T29(4,9) T30(5,9) T31(6,9) T32(7,9) T33(8,9) T34(9,9) T35(10,9) T36(11,9) T37(12,9) T38(13,9) T39(14,9) T40(15,9) T41(16,9) T42(17,9) T43(18,9) T44(19,9) T45(20,9) T46(21,9) T47(22,9) T48(23,9) T49(24,9) U1(-24,8) U2(-23,8) U3(-22,8) U4(-21,8) U5(-20,8) U6(-19,8) U7(-18,8) U8(-17,8) U9(-16,8) U10(-15,8) U11(-14,8) U12(-13,8) U13(-12,8) U14(-11,8) U15(-10,8) U16(-9,8) U17(-8,8) U18(-7,8) U19(-6,8) U20(-5,8) U21(-4,8) U22(-3,8) U23(-2,8) U24(-1,8) U25(0,8) U26(1,8) U27(2,8) U28(3,8) U29(4,8) U30(5,8) U31(6,8) U32(7,8) U33(8,8) U34(9,8) U35(10,8) U36(11,8) U37(12,8) U38(13,8) U39(14,8) U40(15,8) U41(16,8) U42(17,8) U43(18,8) U44(19,8) U45(20,8) U46(21,8) U47(22,8) U48(23,8) U49(24,8) V1(-24,7) V2(-23,7) V3(-22,7) V4(-21,7) V5(-20,7) V6(-19,7) V7(-18,7) V8(-17,7) V9(-16,7) V10(-15,7) V11(-14,7) V12(-13,7) V13(-12,7) V14(-11,7) V15(-10,7) V16(-9,7) V17(-8,7) V18(-7,7) V19(-6,7) V20(-5,7) V21(-4,7) V22(-3,7) V23(-2,7) V24(-1,7) V25(0,7) V26(1,7) V27(2,7) V28(3,7) V29(4,7) V30(5,7) V31(6,7) V32(7,7) V33(8,7) V34(9,7) V35(10,7) V36(11,7) V37(12,7) V38(13,7) V39(14,7) V40(15,7) V41(16,7) V42(17,7) V43(18,7) V44(19,7) V45(20,7) V46(21,7) V47(22,7) V48(23,7) V49(24,7) W1(-24,6) W2(-23,6) W3(-22,6) W4(-21,6) W5(-20,6) W6(-19,6) W7(-18,6) W8(-17,6) W9(-16,6) W10(-15,6) W11(-14,6) W12(-13,6) W13(-12,6) W14(-11,6) W15(-10,6) W16(-9,6) W17(-8,6) W18(-7,6) W19(-6,6) W20(-5,6) W21(-4,6) W22(-3,6) W23(-2,6) W24(-1,6) W25(0,6) W26(1,6) W27(2,6) W28(3,6) W29(4,6) W30(5,6) W31(6,6) W32(7,6) W33(8,6) W34(9,6) W35(10,6) W36(11,6) W37(12,6) W38(13,6) W39(14,6) W40(15,6) W41(16,6) W42(17,6) W43(18,6) W44(19,6) W45(20,6) W46(21,6) W47(22,6) W48(23,6) W49(24,6) Y1(-24,5) Y2(-23,5) Y3(-22,5) Y4(-21,5) Y5(-20,5) Y6(-19,5) Y7(-18,5) Y8(-17,5) Y9(-16,5) Y10(-15,5) Y11(-14,5) Y12(-13,5) Y13(-12,5) Y14(-11,5) Y15(-10,5) Y16(-9,5) Y17(-8,5) Y18(-7,5) Y19(-6,5) Y20(-5,5) Y21(-4,5) Y22(-3,5) Y23(-2,5) Y24(-1,5) Y25(0,5) Y26(1,5) Y27(2,5) Y28(3,5) Y29(4,5) Y30(5,5) Y31(6,5) Y32(7,5) Y33(8,5) Y34(9,5) Y35(10,5) Y36(11,5) Y37(12,5) Y38(13,5) Y39(14,5) Y40(15,5) Y41(16,5) Y42(17,5) Y43(18,5) Y44(19,5) Y45(20,5) Y46(21,5) Y47(22,5) Y48(23,5) Y49(24,5)
Top Overlay:
  circle w0.25: c-25.65,24 r0.125
  region: -24,25 -25,24 -25,25
  lines w0.2: -25,24 -24,25 ; -25,-25 -25,25 25,25 25,-25 -25,-25
Mechanical 13:
  lines w0.1: -25,-25 -25,25 25,25 25,-25 -25,-25
Mechanical 15:
  lines w0.1: -0.5,0 0.5,0 ; 0,-0.5 0,0.5 ; -26,-26 -26,26 26,26 26,-26 -26,-26
3D body: height 0, standoff 0, extent -25,-25 25,25

## BGA127P7X17-119 [mm] "BGA, 119-Leads, Body 22x14mm, Pitch 1.27mm"
height 3.5
pads (119):
  round 0.6 smd: A1(-3.81,10.16) A2(-2.54,10.16) A3(-1.27,10.16) A4(0,10.16) A5(1.27,10.16) A6(2.54,10.16) A7(3.81,10.16) B1(-3.81,8.89) B2(-2.54,8.89) B3(-1.27,8.89) B4(0,8.89) B5(1.27,8.89) B6(2.54,8.89) B7(3.81,8.89) C1(-3.81,7.62) C2(-2.54,7.62) C3(-1.27,7.62) C4(0,7.62) C5(1.27,7.62) C6(2.54,7.62) C7(3.81,7.62) D1(-3.81,6.35) D2(-2.54,6.35) D3(-1.27,6.35) D4(0,6.35) D5(1.27,6.35) D6(2.54,6.35) D7(3.81,6.35) E1(-3.81,5.08) E2(-2.54,5.08) E3(-1.27,5.08) E4(0,5.08) E5(1.27,5.08) E6(2.54,5.08) E7(3.81,5.08) F1(-3.81,3.81) F2(-2.54,3.81) F3(-1.27,3.81) F4(0,3.81) F5(1.27,3.81) F6(2.54,3.81) F7(3.81,3.81) G1(-3.81,2.54) G2(-2.54,2.54) G3(-1.27,2.54) G4(0,2.54) G5(1.27,2.54) G6(2.54,2.54) G7(3.81,2.54) H1(-3.81,1.27) H2(-2.54,1.27) H3(-1.27,1.27) H4(0,1.27) H5(1.27,1.27) H6(2.54,1.27) H7(3.81,1.27) J1(-3.81,0) J2(-2.54,0) J3(-1.27,0) J4(0,0) J5(1.27,0) J6(2.54,0) J7(3.81,0) K1(-3.81,-1.27) K2(-2.54,-1.27) K3(-1.27,-1.27) K4(0,-1.27) K5(1.27,-1.27) K6(2.54,-1.27) K7(3.81,-1.27) L1(-3.81,-2.54) L2(-2.54,-2.54) L3(-1.27,-2.54) L4(0,-2.54) L5(1.27,-2.54) L6(2.54,-2.54) L7(3.81,-2.54) M1(-3.81,-3.81) M2(-2.54,-3.81) M3(-1.27,-3.81) M4(0,-3.81) M5(1.27,-3.81) M6(2.54,-3.81) M7(3.81,-3.81) N1(-3.81,-5.08) N2(-2.54,-5.08) N3(-1.27,-5.08) N4(0,-5.08) N5(1.27,-5.08) N6(2.54,-5.08) N7(3.81,-5.08) P1(-3.81,-6.35) P2(-2.54,-6.35) P3(-1.27,-6.35) P4(0,-6.35) P5(1.27,-6.35) P6(2.54,-6.35) P7(3.81,-6.35) R1(-3.81,-7.62) R2(-2.54,-7.62) R3(-1.27,-7.62) R4(0,-7.62) R5(1.27,-7.62) R6(2.54,-7.62) R7(3.81,-7.62) T1(-3.81,-8.89) T2(-2.54,-8.89) T3(-1.27,-8.89) T4(0,-8.89) T5(1.27,-8.89) T6(2.54,-8.89) T7(3.81,-8.89) U1(-3.81,-10.16) U2(-2.54,-10.16) U3(-1.27,-10.16) U4(0,-10.16) U5(1.27,-10.16) U6(2.54,-10.16) U7(3.81,-10.16)
Top Overlay:
  circle w0.25: c-7.65,10.16 r0.125
  region: -6,11 -7,10 -7,11
  lines w0.2: -7,10 -6,11 ; -7,-11 -7,11 7,11 7,-11 -7,-11
Mechanical 13:
  lines w0.1: -7,-11 -7,11 7,11 7,-11 -7,-11
Mechanical 15:
  lines w0.1: -0.5,0 0.5,0 ; 0,-0.5 0,0.5 ; -8,-12 -8,12 8,12 8,-12 -8,-12
3D body: height 3.5, standoff 0, extent -7,-11 7,11

## BGA127P9X17-153 [mm] "BGA, 153-Leads, Body 22x14mm, Pitch 1.27mm"
height 3.5
pads (153):
  round 0.6 smd: A1(-5.08,10.16) A2(-3.81,10.16) A3(-2.54,10.16) A4(-1.27,10.16) A5(0,10.16) A6(1.27,10.16) A7(2.54,10.16) A8(3.81,10.16) A9(5.08,10.16) B1(-5.08,8.89) B2(-3.81,8.89) B3(-2.54,8.89) B4(-1.27,8.89) B5(0,8.89) B6(1.27,8.89) B7(2.54,8.89) B8(3.81,8.89) B9(5.08,8.89) C1(-5.08,7.62) C2(-3.81,7.62) C3(-2.54,7.62) C4(-1.27,7.62) C5(0,7.62) C6(1.27,7.62) C7(2.54,7.62) C8(3.81,7.62) C9(5.08,7.62) D1(-5.08,6.35) D2(-3.81,6.35) D3(-2.54,6.35) D4(-1.27,6.35) D5(0,6.35) D6(1.27,6.35) D7(2.54,6.35) D8(3.81,6.35) D9(5.08,6.35) E1(-5.08,5.08) E2(-3.81,5.08) E3(-2.54,5.08) E4(-1.27,5.08) E5(0,5.08) E6(1.27,5.08) E7(2.54,5.08) E8(3.81,5.08) E9(5.08,5.08) F1(-5.08,3.81) F2(-3.81,3.81) F3(-2.54,3.81) F4(-1.27,3.81) F5(0,3.81) F6(1.27,3.81) F7(2.54,3.81) F8(3.81,3.81) F9(5.08,3.81) G1(-5.08,2.54) G2(-3.81,2.54) G3(-2.54,2.54) G4(-1.27,2.54) G5(0,2.54) G6(1.27,2.54) G7(2.54,2.54) G8(3.81,2.54) G9(5.08,2.54) H1(-5.08,1.27) H2(-3.81,1.27) H3(-2.54,1.27) H4(-1.27,1.27) H5(0,1.27) H6(1.27,1.27) H7(2.54,1.27) H8(3.81,1.27) H9(5.08,1.27) J1(-5.08,0) J2(-3.81,0) J3(-2.54,0) J4(-1.27,0) J5(0,0) J6(1.27,0) J7(2.54,0) J8(3.81,0) J9(5.08,0) K1(-5.08,-1.27) K2(-3.81,-1.27) K3(-2.54,-1.27) K4(-1.27,-1.27) K5(0,-1.27) K6(1.27,-1.27) K7(2.54,-1.27) K8(3.81,-1.27) K9(5.08,-1.27) L1(-5.08,-2.54) L2(-3.81,-2.54) L3(-2.54,-2.54) L4(-1.27,-2.54) L5(0,-2.54) L6(1.27,-2.54) L7(2.54,-2.54) L8(3.81,-2.54) L9(5.08,-2.54) M1(-5.08,-3.81) M2(-3.81,-3.81) M3(-2.54,-3.81) M4(-1.27,-3.81) M5(0,-3.81) M6(1.27,-3.81) M7(2.54,-3.81) M8(3.81,-3.81) M9(5.08,-3.81) N1(-5.08,-5.08) N2(-3.81,-5.08) N3(-2.54,-5.08) N4(-1.27,-5.08) N5(0,-5.08) N6(1.27,-5.08) N7(2.54,-5.08) N8(3.81,-5.08) N9(5.08,-5.08) P1(-5.08,-6.35) P2(-3.81,-6.35) P3(-2.54,-6.35) P4(-1.27,-6.35) P5(0,-6.35) P6(1.27,-6.35) P7(2.54,-6.35) P8(3.81,-6.35) P9(5.08,-6.35) R1(-5.08,-7.62) R2(-3.81,-7.62) R3(-2.54,-7.62) R4(-1.27,-7.62) R5(0,-7.62) R6(1.27,-7.62) R7(2.54,-7.62) R8(3.81,-7.62) R9(5.08,-7.62) T1(-5.08,-8.89) T2(-3.81,-8.89) T3(-2.54,-8.89) T4(-1.27,-8.89) T5(0,-8.89) T6(1.27,-8.89) T7(2.54,-8.89) T8(3.81,-8.89) T9(5.08,-8.89) U1(-5.08,-10.16) U2(-3.81,-10.16) U3(-2.54,-10.16) U4(-1.27,-10.16) U5(0,-10.16) U6(1.27,-10.16) U7(2.54,-10.16) U8(3.81,-10.16) U9(5.08,-10.16)
Top Overlay:
  circle w0.25: c-7.658,10.16 r0.125
  region: -6.008,11.005 -7.008,10.005 -7.008,11.005
  lines w0.2: -7.008,10.005 -6.008,11.005 ; -7.008,-10.995 6.993,-10.995 6.993,11.005 -7.008,11.005 -7.008,-10.995
Mechanical 13:
  lines w0.1: -7.008,-10.995 6.993,-10.995 6.993,11.005 -7.008,11.005 -7.008,-10.995
Mechanical 15:
  lines w0.1: -0.507,0.005 0.492,0.005 ; -0.008,-0.495 -0.008,0.505 ; -8.007,-11.995 7.992,-11.995 7.992,12.005 -8.007,12.005 -8.007,-11.995
3D body: height 3.5, standoff 0, extent -7.007,-10.995 6.993,11.005

## BGA127P11X19-209 [mm] "BGA, 209-Leads, Body 25x21mm, Pitch 1.27mm"
height 3.5
pads (209):
  round 0.6 smd: A1(-6.35,11.43) A2(-5.08,11.43) A3(-3.81,11.43) A4(-2.54,11.43) A5(-1.27,11.43) A6(0,11.43) A7(1.27,11.43) A8(2.54,11.43) A9(3.81,11.43) A10(5.08,11.43) A11(6.35,11.43) B1(-6.35,10.16) B2(-5.08,10.16) B3(-3.81,10.16) B4(-2.54,10.16) B5(-1.27,10.16) B6(0,10.16) B7(1.27,10.16) B8(2.54,10.16) B9(3.81,10.16) B10(5.08,10.16) B11(6.35,10.16) C1(-6.35,8.89) C2(-5.08,8.89) C3(-3.81,8.89) C4(-2.54,8.89) C5(-1.27,8.89) C6(0,8.89) C7(1.27,8.89) C8(2.54,8.89) C9(3.81,8.89) C10(5.08,8.89) C11(6.35,8.89) D1(-6.35,7.62) D2(-5.08,7.62) D3(-3.81,7.62) D4(-2.54,7.62) D5(-1.27,7.62) D6(0,7.62) D7(1.27,7.62) D8(2.54,7.62) D9(3.81,7.62) D10(5.08,7.62) D11(6.35,7.62) E1(-6.35,6.35) E2(-5.08,6.35) E3(-3.81,6.35) E4(-2.54,6.35) E5(-1.27,6.35) E6(0,6.35) E7(1.27,6.35) E8(2.54,6.35) E9(3.81,6.35) E10(5.08,6.35) E11(6.35,6.35) F1(-6.35,5.08) F2(-5.08,5.08) F3(-3.81,5.08) F4(-2.54,5.08) F5(-1.27,5.08) F6(0,5.08) F7(1.27,5.08) F8(2.54,5.08) F9(3.81,5.08) F10(5.08,5.08) F11(6.35,5.08) G1(-6.35,3.81) G2(-5.08,3.81) G3(-3.81,3.81) G4(-2.54,3.81) G5(-1.27,3.81) G6(0,3.81) G7(1.27,3.81) G8(2.54,3.81) G9(3.81,3.81) G10(5.08,3.81) G11(6.35,3.81) H1(-6.35,2.54) H2(-5.08,2.54) H3(-3.81,2.54) H4(-2.54,2.54) H5(-1.27,2.54) H6(0,2.54) H7(1.27,2.54) H8(2.54,2.54) H9(3.81,2.54) H10(5.08,2.54) H11(6.35,2.54) J1(-6.35,1.27) J2(-5.08,1.27) J3(-3.81,1.27) J4(-2.54,1.27) J5(-1.27,1.27) J6(0,1.27) J7(1.27,1.27) J8(2.54,1.27) J9(3.81,1.27) J10(5.08,1.27) J11(6.35,1.27) K1(-6.35,0) K2(-5.08,0) K3(-3.81,0) K4(-2.54,0) K5(-1.27,0) K6(0,0) K7(1.27,0) K8(2.54,0) K9(3.81,0) K10(5.08,0) K11(6.35,0) L1(-6.35,-1.27) L2(-5.08,-1.27) L3(-3.81,-1.27) L4(-2.54,-1.27) L5(-1.27,-1.27) L6(0,-1.27) L7(1.27,-1.27) L8(2.54,-1.27) L9(3.81,-1.27) L10(5.08,-1.27) L11(6.35,-1.27) M1(-6.35,-2.54) M2(-5.08,-2.54) M3(-3.81,-2.54) M4(-2.54,-2.54) M5(-1.27,-2.54) M6(0,-2.54) M7(1.27,-2.54) M8(2.54,-2.54) M9(3.81,-2.54) M10(5.08,-2.54) M11(6.35,-2.54) N1(-6.35,-3.81) N2(-5.08,-3.81) N3(-3.81,-3.81) N4(-2.54,-3.81) N5(-1.27,-3.81) N6(0,-3.81) N7(1.27,-3.81) N8(2.54,-3.81) N9(3.81,-3.81) N10(5.08,-3.81) N11(6.35,-3.81) P1(-6.35,-5.08) P2(-5.08,-5.08) P3(-3.81,-5.08) P4(-2.54,-5.08) P5(-1.27,-5.08) P6(0,-5.08) P7(1.27,-5.08) P8(2.54,-5.08) P9(3.81,-5.08) P10(5.08,-5.08) P11(6.35,-5.08) R1(-6.35,-6.35) R2(-5.08,-6.35) R3(-3.81,-6.35) R4(-2.54,-6.35) R5(-1.27,-6.35) R6(0,-6.35) R7(1.27,-6.35) R8(2.54,-6.35) R9(3.81,-6.35) R10(5.08,-6.35) R11(6.35,-6.35) T1(-6.35,-7.62) T2(-5.08,-7.62) T3(-3.81,-7.62) T4(-2.54,-7.62) T5(-1.27,-7.62) T6(0,-7.62) T7(1.27,-7.62) T8(2.54,-7.62) T9(3.81,-7.62) T10(5.08,-7.62) T11(6.35,-7.62) U1(-6.35,-8.89) U2(-5.08,-8.89) U3(-3.81,-8.89) U4(-2.54,-8.89) U5(-1.27,-8.89) U6(0,-8.89) U7(1.27,-8.89) U8(2.54,-8.89) U9(3.81,-8.89) U10(5.08,-8.89) U11(6.35,-8.89) V1(-6.35,-10.16) V2(-5.08,-10.16) V3(-3.81,-10.16) V4(-2.54,-10.16) V5(-1.27,-10.16) V6(0,-10.16) V7(1.27,-10.16) V8(2.54,-10.16) V9(3.81,-10.16) V10(5.08,-10.16) V11(6.35,-10.16) W1(-6.35,-11.43) W2(-5.08,-11.43) W3(-3.81,-11.43) W4(-2.54,-11.43) W5(-1.27,-11.43) W6(0,-11.43) W7(1.27,-11.43) W8(2.54,-11.43) W9(3.81,-11.43) W10(5.08,-11.43) W11(6.35,-11.43)
Top Overlay:
  circle w0.25: c-11.15,11.43 r0.125
  region: -9.5,12.5 -10.5,11.5 -10.5,12.5
  lines w0.2: -10.5,11.5 -9.5,12.5 ; -10.5,-12.5 10.5,-12.5 10.5,12.5 -10.5,12.5 -10.5,-12.5
Mechanical 13:
  lines w0.1: -10.5,-12.5 10.5,-12.5 10.5,12.5 -10.5,12.5 -10.5,-12.5
Mechanical 15:
  lines w0.1: -0.5,0 0.5,0 ; 0,-0.5 0,0.5 ; -11.5,-13.5 11.5,-13.5 11.5,13.5 -11.5,13.5 -11.5,-13.5
3D body: height 3.5, standoff 0, extent -10.5,-12.5 10.5,12.5

## BNC_RA CON [mm] "Connector; BNC Elbow"
pads (4):
  rect 1.5x1.5 hole 0.9: 1(0,0)
  round 3.3 hole 2: 2(-5.1,-5.1) 2(-5.1,5.1)
  round 1.5 hole 0.9: 2(0,-2.5)
Top Overlay:
  circle w0.025: c-28.9,0 r1
  lines w0.025: -20.1,-6.25 -21.1,6.25 ; -20.1,6.25 -19.1,-6.25 ; -19.1,6.25 -18.1,-6.25 ; -18.1,6.25 -17.1,-6.25 ; -17.1,6.25 -16.1,-6.25 ; -16.1,6.25 -15.1,-6.25 ; -15.1,6.25 -14.1,-6.25 ; -14.1,6.25 -13.1,-6.25 ; -21.1,-4.8 -21.1,-6.25 -12.2,-6.25 ; -21.1,-4.8 -21.1,4.8 ; -21.1,-4.8 -33,-4.8 -33,4.8 -21.1,4.8 ; -21.1,4.8 -21.1,6.25 ; -21.1,6.25 -12.2,6.25 ; -12.2,-6.25 -12.2,-7.4 1.9,-7.4 1.9,7.4 -12.2,7.4 -12.2,6.25 ; -12.2,-6.25 -12.2,6.25 ; -11,-5.9 -11,5.9 -3,5.9 -3,-5.9 -11,-5.9
  lines w0.2: -21.1,-4.8 -21.1,-6.25 -12.2,-6.25 ; -21.1,-4.8 -33,-4.8 -33,4.8 -21.1,4.8 ; -21.1,-4.8 -21.1,4.8 ; -21.1,4.8 -21.1,6.25 -12.2,6.25 ; -12.2,-6.25 -12.2,-7.4 1.9,-7.4 1.9,7.4 -12.2,7.4 -12.2,6.25 ; -12.2,-6.25 -12.2,6.25

## Buzzer 5v [mil]
height 354.33
pads (3):
  round 20 on Mech14: 0(0,0)
  rrect25% 72x72 / inner rrect25% 72x72 / far side rrect25% 90x90 hole 38: 1(-161.42,3.94)
  round 72 / inner round 72 / far side round 90 hole 38: 2(137.8,3.94)
Top Overlay:
  circle w10: c0,0 r300
  lines w5: -370,-0.94 -335.35,-0.94 ; -350,-20 -350,20
Mechanical 13:
  lines w3: 236.36,-0.47 cw(c0.14,-0.47) 236.36,-0.03
Mechanical 14:
  circle w3: c0,0 r246.06
3D body: height 670.87, standoff -195.28, extent -324.96,-314.95 304.96,314.97

## BUZZER_12.0X8.5MM [mil]
height 354.33
pads (3):
  round 20 on Mech14: 0(0,0)
  rrect25% 72x72 / inner rrect25% 72x72 / far side rrect25% 90x90 hole 38: 1(-127.95,0)
  round 72 / inner round 72 / far side round 90 hole 38: 2(127.95,0)
Top Overlay:
  circle w5: c0,0 r236.22
  lines w5: -148.27,66.93 -108.27,66.93 ; -128.02,45.87 -128.02,85.87
Mechanical 13:
  circle w3: c0.14,-0.47 r236.22
Mechanical 14:
  circle w3: c0,0 r246.06
3D body: height 50, standoff 0, extent -172.59,-44.91 -82.95,44.92
3D body: height 50, standoff 0, extent 83.31,-44.9 172.96,44.92
3D body: height 354.33, standoff -110.24, extent -246.02,-246.04 246.07,246.06

## C0805 [mm] "Chip Capacitor, Body 2.0x1.3mm, IPC High Density"
height 1.4
pads (2):
  rect 1.1x1.4 smd: 1(-0.801,0) 2(0.801,0)
Top Overlay:
  lines w0.1: -1.778,-1.143 1.778,-1.143 1.778,1.143 -1.778,1.143 -1.778,-1.143
Mechanical 13:
  lines w0.1: -1.1,-0.725 1.1,-0.725 1.1,0.725 -1.1,0.725 -1.1,-0.725
Mechanical 15:
  lines w0.1: -0.5,0 0.5,0 ; 0,-0.5 0,0.5
3D body: height 1.4, standoff 0, extent -1.1,-0.725 1.1,0.725

## C1206 [mm] "Chip Capacitor, Body 3.2x1.6mm, IPC High Density"
height 1.3
pads (2):
  rect 1.1x1.7 smd: 1(-1.35,0) 2(1.35,0)
Top Overlay:
  lines w0.2: -0.4,-0.75 0.4,-0.75 ; -0.4,0.75 0.4,0.75
Mechanical 13:
  lines w0.1: -1.7,-0.9 1.7,-0.9 1.7,0.9 -1.7,0.9 -1.7,-0.9
Mechanical 15:
  lines w0.1: -0.5,0 0.5,0 ; 0,-0.5 0,0.5 ; -2,-0.95 2,-0.95 2,0.95 -2,0.95 -2,-0.95
3D body: height 1.3, standoff 0, extent -1.7,-0.9 1.7,0.9

## C1210 [mm] "Chip Capacitor, Body 3.2x2.5mm, IPC High Density"
height 1.3
pads (2):
  rect 1.1x2.6 smd: 1(-1.35,0) 2(1.35,0)
Top Overlay:
  lines w0.2: -0.4,-1.2 0.4,-1.2 ; -0.4,1.2 0.4,1.2
Mechanical 13:
  lines w0.1: -1.7,-1.35 1.7,-1.35 1.7,1.35 -1.7,1.35 -1.7,-1.35
Mechanical 15:
  lines w0.1: -0.5,0 0.5,0 ; 0,-0.5 0,0.5 ; -2,-1.4 2,-1.4 2,1.4 -2,1.4 -2,-1.4
3D body: height 1.3, standoff 0, extent -1.7,-1.35 1.7,1.35

## C1210_L [mm] "Chip Capacitor, Body 3.2x2.5mm, IPC High Density"
height 1.5
pads (2):
  rect 1.1x2.6 smd: 1(-1.35,0) 2(1.35,0)
Top Overlay:
  lines w0.2: -0.4,-1.2 0.4,-1.2 ; -0.4,1.2 0.4,1.2
Mechanical 13:
  lines w0.1: -1.7,-1.35 1.7,-1.35 1.7,1.35 -1.7,1.35 -1.7,-1.35
Mechanical 15:
  lines w0.1: -0.5,0 0.5,0 ; 0,-0.5 0,0.5 ; -2,-1.4 2,-1.4 2,1.4 -2,1.4 -2,-1.4
3D body: height 1.5, standoff 0, extent -1.7,-1.35 1.7,1.35

## C1210_M [mm] "Chip Capacitor, Body 3.2x2.5mm, IPC Low Density"
height 1.5
pads (2):
  rect 1.5x2.8 smd: 1(-1.55,0) 2(1.55,0)
Top Overlay:
  lines w0.2: -0.4,-1.3 0.4,-1.3 ; -0.4,1.3 0.4,1.3
Mechanical 13:
  lines w0.1: -1.7,-1.35 -1.7,1.35 1.7,1.35 1.7,-1.35 -1.7,-1.35
Mechanical 15:
  lines w0.1: -0.5,0 0.5,0 ; 0,-0.5 0,0.5 ; -2.8,-1.9 -2.8,1.9 2.8,1.9 2.8,-1.9 -2.8,-1.9
3D body: height 1.5, standoff 0, extent -1.7,-1.35 1.7,1.35

## C1210_N [mm] "Chip Capacitor, Body 3.2x2.5mm, IPC Medium Density"
height 1.5
pads (2):
  rect 1.3x2.7 smd: 1(-1.45,0) 2(1.45,0)
Top Overlay:
  lines w0.2: -0.4,-1.25 0.4,-1.25 ; -0.4,1.25 0.4,1.25
Mechanical 13:
  lines w0.1: -1.7,-1.35 -1.7,1.35 1.7,1.35 1.7,-1.35 -1.7,-1.35
Mechanical 15:
  lines w0.1: -0.5,0 0.5,0 ; 0,-0.5 0,0.5 ; -2.35,-1.6 -2.35,1.6 2.35,1.6 2.35,-1.6 -2.35,-1.6
3D body: height 1.5, standoff 0, extent -1.7,-1.35 1.7,1.35

## C2225 [mm] "Chip Capacitor, Body 5.7x6.4mm, IPC High Density"
height 1.4
pads (2):
  rect 1.4x6.7 smd: 1(-2.5,0) 2(2.5,0)
Top Overlay:
  lines w0.2: -1.4,-3.25 1.4,-3.25 ; -1.4,3.25 1.4,3.25
Mechanical 13:
  lines w0.1: -2.95,-3.4 -2.95,3.4 2.95,3.4 2.95,-3.4 -2.95,-3.4
Mechanical 15:
  lines w0.1: -0.5,0 0.5,0 ; 0,-0.5 0,0.5 ; -3.3,-3.45 -3.3,3.45 3.3,3.45 3.3,-3.45 -3.3,-3.45
3D body: height 1.4, standoff 0, extent -2.95,-3.4 2.95,3.4

## C2512 [mm] "Chip Capacitor, Body 2.54x1.27mm, IPC High Density"
height 1.3
pads (2):
  rect 1.4x1.4 smd: 1(-0.9,0) 2(0.9,0)
Top Overlay:
  lines w0.2: -1.9,-0.6 -1.9,0.6
Mechanical 13:
  lines w0.1: -1.45,-0.825 1.45,-0.825 1.45,0.825 -1.45,0.825 -1.45,-0.825
Mechanical 15:
  lines w0.1: -0.5,0 0.5,0 ; 0,-0.5 0,0.5 ; -1.7,-0.8 1.7,-0.8 1.7,0.8 -1.7,0.8 -1.7,-0.8
3D body: height 1.3, standoff 0, extent -1.45,-0.825 1.45,0.825

## CAN-2 [mm] "Can; 2 Leads; Pin Circle Dia. 2.54 mm; Lead Dia. 0.48 mm (max)"
height 3.81
pads (2):
  rect 1.4x1.4 hole 0.8: 1(-1.27,0)
  round 1.4 hole 0.8: 2(1.27,0)
Top Overlay:
  lines w0.2: -3.386,2.537 -2.537,3.386 -1.618,2.467 cw(c0,0) -2.467,1.618 -3.386,2.537
  text "2" at 3.813,-0.645 h1.5
  text "1" at -4.393,-0.645 h1.5
Mechanical 13:
  circle w0.1: c0,0 r2.95
Mechanical 15:
  lines w0.1: -0.5,0 0.5,0 ; 0,-0.5 0,0.5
